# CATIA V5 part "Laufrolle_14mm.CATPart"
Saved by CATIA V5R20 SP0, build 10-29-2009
Part number: Laufrolle_14mm
Bounding box of the stored display mesh (mm): x -19.95 to 19.95, y -19.949 to 19.949, z -10 to 10
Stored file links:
  C:\Users\Andi\Desktop\Plasma\Laufrolle_14mm.CATPart
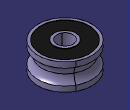
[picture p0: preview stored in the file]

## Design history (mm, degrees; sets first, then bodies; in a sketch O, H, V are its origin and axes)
Body1 (main body)
  Sketch1 on yz-plane, origin (0, 0, 0), H (0, 1, 0), V (0, 0, 1)
    axis line L1 (0, 19.9273) -> (0, -23.0147)
    point P1 (0, 19.9273)
    arc A1 centre (24, 0) radius 7 from (19.95, 5.7094) to (17, 0) ccw
    point P3 (24, 0)
    point P4 (19.95, 5.7094)
    line L2 (19.95, 5.7094) -> (19.95, 9.75)
    point P5 (6, 10)
    line L3 (6, 10) -> (6, 0)
    point P6 (6, 0)
    construction line L4 (35.4118, 0) -> (-5.8584, 0)
    point P7 (35.4118, 0)
    point P9 (17, 0)
    line L5 (17.95, 9.5) -> (8, 9.5)
    point P10 (8, 9.5)
    line L6 (8, 9.5) -> (8, 10)
    point P11 (8, 10)
    line L7 (8, 10) -> (6, 10)
    point P12 (17, 0)
    point P13 (19.95, -5.7094)
    point P14 (24, 0)
    arc A2 centre (24, 0) radius 7 from (19.95, -5.7094) to (17, 0) cw
    line L8 (19.95, -5.7094) -> (19.95, -9.75)
    point P15 (8, -9.5)
    line L9 (17.95, -9.5) -> (8, -9.5)
    point P16 (8, -10)
    line L10 (8, -9.5) -> (8, -10)
    point P17 (6, -10)
    line L11 (8, -10) -> (6, -10)
    point P18 (6, 0)
    line L12 (6, -10) -> (6, 0)
    line L13 (17.95, 9.5) -> (17.95, 9.75)
    line L14 (17.95, 9.75) -> (19.95, 9.75)
    line L15 (17.95, -9.5) -> (17.95, -9.75)
    line L16 (17.95, -9.75) -> (19.95, -9.75)
    distance L2 L1 = 19.95
    radius A1 = 7
    distance L3 L1 = 6
    distance P14 L1 = 24
    distance L7 L11 = 20
    distance L6 L3 = 2
    distance L13 L2 = 2 {= Sketch1.distance(L6 L3)}
    distance L5 L7 = 0.5
    distance L16 L14 = 19.5
    coincidence: P1 V, P3 H, P6 H, P7 H, L4 P9, P6 P18, P9 P12, L15 L13
    vertical: L1 V, L2 V, L3 V, L6 V, L13 V, L15 V
    horizontal: L4 H, L5 H, L7 H, L14 H, L16 H
    symmetry: P9 P12 L4, P4 P13 L4, A1 A2 L4, L2 L8 L4, P10 P15 L4, L5 L9 L4, P11 P16 L4, L6 L10 L4, P5 P17 L4, L7 L11 L4, P6 P18 L4, L3 L12 L4, L16 L14 L4
  Shaft1: profile Sketch1, axis Sketch1.L1, angle 360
